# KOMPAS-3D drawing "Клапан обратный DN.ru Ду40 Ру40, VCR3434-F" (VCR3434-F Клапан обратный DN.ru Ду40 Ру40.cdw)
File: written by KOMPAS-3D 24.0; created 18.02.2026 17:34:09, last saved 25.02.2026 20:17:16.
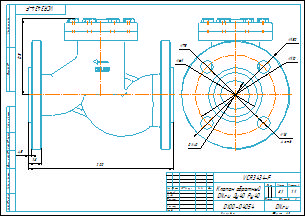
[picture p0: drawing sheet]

Document properties: art: D100-04054; Автор: R2D2; Форматы листов документа: A3; Полное имя файла: VCR3434-F Клапан обратный DN.ru Ду40 Ру40.m3d; Масса: 8.1; Наименование: Клапан обратный DN.ru Ду40 Ру40; Количество листов документа: 1; Примечание: D100-04054

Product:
- Part/product: Клапан обратный DN.ru Ду40 Ру40  | designation VCR3434-F
    Масса: 8.1
    Раздел спецификации: Прочие изделия
    Примечание: D100-04054
    additional columns: D100-04054

Views: Вид 1, Спереди
Referenced files in E:\Работа\Зайцев\VCR3434-F Клапан обратный DN.ru Ду15-300\DN40\: VCR3434-F Клапан обратный DN.ru Ду40 Ру40.m3d
Referenced files in E:\Работа\Зайцев\Для компаса\: чертеж DN.ru А3.cdt
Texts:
  VCR3434-F
  чертеж DN.ru А3.cdt
  Клапан обратный
  DN.ru Ду40 Ру40
  prop
  Клапан обратный DN.ru Ду40 Ру40
  VCR3434-F Клапан обратный DN.ru Ду40 Ру40
Dimensions and other numbers on the sheet: 0; 3; 2; 4; 150; 110; 18; 4 отв.; 40; 61; 75; 1:1; 1; 8,1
